(* Logix 5000 project; controller Motion_Axis_AOIs_AMCI_RSLogix_V31 vendor 1 type 14 code 108 rev 31.11; software revision 31.02; part 7 of 7 *)
(* tags used below, declared in another part *)
   AMCI_MA_Circular_Follower_SMD34E2 : AMCI_MA_SD_SMD_Circular_Follower;
   AMCI_MA_Linear_Follower_SMD34E2 : AMCI_MA_SD_SMD_Linear_Follower;
   AMCI_MA_Reset_Driver_Fault : AMCI_MA_Reset_Driver_Fault;
   AMCI_MA_Reset_Driver_Faults_SMD34E2 : AMCI_MA_Reset_Driver_Fault;
   AMCI_MAFR_SMD34E2 : AMCI_MAFR;
   AMCI_MAFR_SV160E2 : AMCI_MAFR;
   AMCI_MAFR_SV400E2 : AMCI_MAFR;
   AMCI_MAH_SMD34E2 : AMCI_MAH;
   AMCI_MAH_SV160E2 : AMCI_MAH;
   AMCI_MAH_SV400E2 : AMCI_MAH;
   AMCI_MAJ_SMD34E2 : AMCI_MAJ;
   AMCI_MAJ_SV160E2 : AMCI_MAJ;
   AMCI_MAJ_SV400E2 : AMCI_MAJ;
   AMCI_MAM_SMD34E2 : AMCI_MAM;
   AMCI_MAM_SV160E2 : AMCI_MAM;
   AMCI_MAM_SV400E2 : AMCI_MAM;
   AMCI_MAS_SMD34E2 : AMCI_MAS;
   AMCI_MAS_SV160E2 : AMCI_MAS;
   AMCI_MAS_SV400E2 : AMCI_MAS;
   AMCI_MRP_SMD34E2 : AMCI_MRP;
   AMCI_MRP_SV160E2 : AMCI_MRP;
   AMCI_MRP_SV400E2 : AMCI_MRP;
   AMCI_MSO_Preset_to_Absolute_Encoder : AMCI_MSO_and_Preset_to_Absolute_Encoder;
   AMCI_SV160E2_Circular_Follower : AMCI_MA_SV_Circular_Follower;
   AMCI_SV16E2_Linear_Follower : AMCI_MA_SV_Linear_Follower;
   AMCI_SV400E2_Circular_Follower : AMCI_MA_SV_Circular_Follower;
   AMCI_SV400E2_Linear_Follower : AMCI_MA_SV_Linear_Follower;
   AMCI_SMD34E2_input_data : AMCI_Motion_Axis_Input_Data;
   AMCI_SMD34E2_output_data : AMCI_Motion_Axis_Output_Data;
   AMCI_SV160E2_input_data : AMCI_Motion_Axis_Input_Data;
   AMCI_SV160E2_output_data : AMCI_Motion_Axis_Output_Data;
   AMCI_SV4000E2_input_data : AMCI_Motion_Axis_Input_Data;
   AMCI_SV400E2_output_data : AMCI_Motion_Axis_Output_Data;
   comment_coil : DINT;
   Main_Power : BOOL;   // 0=Remove Main Power 1=Apply Main Power
   Run_AMCI_SMD34E2 : DINT;
   Run_AMCI_SV160E2 : DINT;
   Run_AMCI_SV400E2 : DINT;
   Sample_Motion_Axis : AXIS_VIRTUAL;
(* MainProgram, continued *)

ROUTINE SMD34E2   (* ladder *)
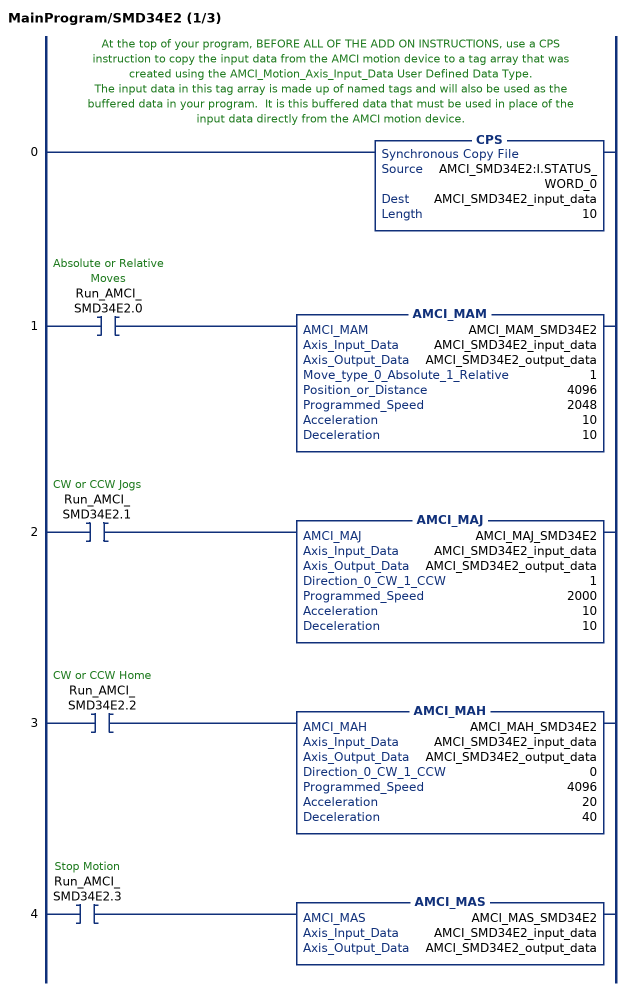
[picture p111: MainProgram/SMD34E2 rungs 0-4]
   // At the top of your program, BEFORE ALL OF THE ADD ON INSTRUCTIONS, use a CPS instruction to copy the input data from the AMCI motion device to a tag array that was created using the AMCI_Motion_Axis_Input_Data User Defined Data Type.
   // The input data in this tag array is made up of named tags and will also be used as the buffered data in your program.  It is this buffered data that must be used in place of the input data directly from the AMCI motion device.
   0: CPS(AMCI_SMD34E2:I.STATUS_WORD_0,AMCI_SMD34E2_input_data,10);
   1: XIC(Run_AMCI_SMD34E2.0)AMCI_MAM(AMCI_MAM_SMD34E2,AMCI_SMD34E2_input_data,AMCI_SMD34E2_output_data,1,4096,2048,10,10);
   2: XIC(Run_AMCI_SMD34E2.1)AMCI_MAJ(AMCI_MAJ_SMD34E2,AMCI_SMD34E2_input_data,AMCI_SMD34E2_output_data,1,2000,10,10);
   3: XIC(Run_AMCI_SMD34E2.2)AMCI_MAH(AMCI_MAH_SMD34E2,AMCI_SMD34E2_input_data,AMCI_SMD34E2_output_data,0,4096,20,40);
   4: XIC(Run_AMCI_SMD34E2.3)AMCI_MAS(AMCI_MAS_SMD34E2,AMCI_SMD34E2_input_data,AMCI_SMD34E2_output_data);
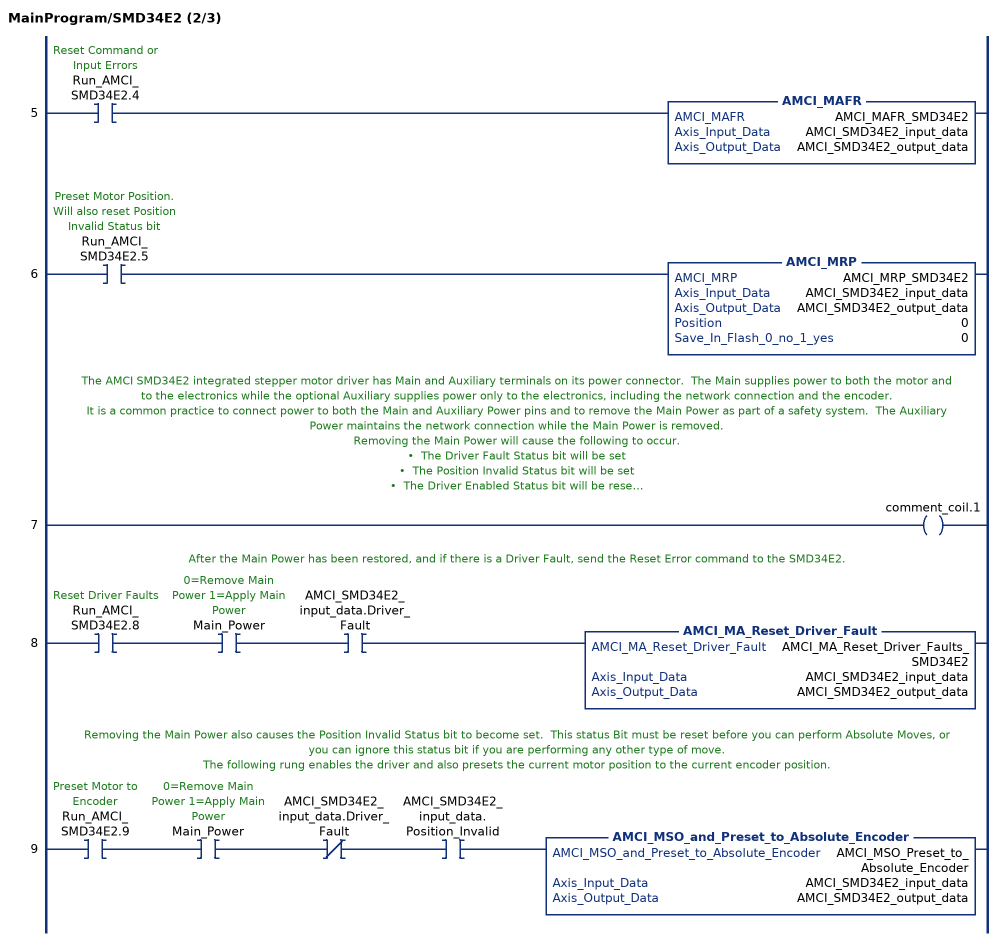
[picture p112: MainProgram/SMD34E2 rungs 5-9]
   5: XIC(Run_AMCI_SMD34E2.4)AMCI_MAFR(AMCI_MAFR_SMD34E2,AMCI_SMD34E2_input_data,AMCI_SMD34E2_output_data);
   6: XIC(Run_AMCI_SMD34E2.5)AMCI_MRP(AMCI_MRP_SMD34E2,AMCI_SMD34E2_input_data,AMCI_SMD34E2_output_data,0,0);
   // The AMCI SMD34E2 integrated stepper motor driver has Main and Auxiliary terminals on its power connector.  The Main supplies power to both the motor and to the electronics while the optional Auxiliary supplies power only to the electronics, including the network connection and the encoder.
   // It is a common practice to connect power to both the Main and Auxiliary Power pins and to remove the Main Power as part of a safety system.  The Auxiliary Power maintains the network connection while the Main Power is removed.
   // Removing the Main Power will cause the following to occur.
   // •	The Driver Fault Status bit will be set
   // •	The Position Invalid Status bit will be set
   // •	The Driver Enabled Status bit will be reset
   // The following two rungs show the action that you should take while the Main Power is removed and the steps needed to recover after the Main Power has been restored.
   7: OTE(comment_coil.1);
   // After the Main Power has been restored, and if there is a Driver Fault, send the Reset Error command to the SMD34E2.
   8: XIC(Run_AMCI_SMD34E2.8)XIC(Main_Power)XIC(AMCI_SMD34E2_input_data.Driver_Fault)AMCI_MA_Reset_Driver_Fault(AMCI_MA_Reset_Driver_Faults_SMD34E2,AMCI_SMD34E2_input_data,AMCI_SMD34E2_output_data);
   // Removing the Main Power also causes the Position Invalid Status bit to become set.  This status Bit must be reset before you can perform Absolute Moves, or you can ignore this status bit if you are performing any other type of move.
   // The following rung enables the driver and also presets the current motor position to the current encoder position.
   9: XIC(Run_AMCI_SMD34E2.9)XIC(Main_Power)XIO(AMCI_SMD34E2_input_data.Driver_Fault)XIC(AMCI_SMD34E2_input_data.Position_Invalid)AMCI_MSO_and_Preset_to_Absolute_Encoder(AMCI_MSO_Preset_to_Absolute_Encoder,AMCI_SMD34E2_input_data,AMCI_SMD34E2_output_data);
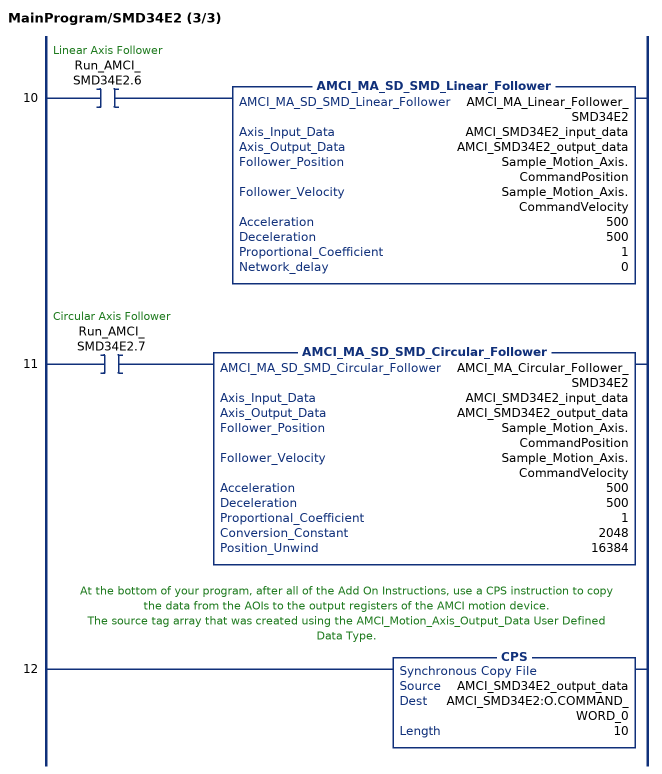
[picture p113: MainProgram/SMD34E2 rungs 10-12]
   10: XIC(Run_AMCI_SMD34E2.6)AMCI_MA_SD_SMD_Linear_Follower(AMCI_MA_Linear_Follower_SMD34E2,AMCI_SMD34E2_input_data,AMCI_SMD34E2_output_data,Sample_Motion_Axis.CommandPosition,Sample_Motion_Axis.CommandVelocity,500,500,1,0);
   11: XIC(Run_AMCI_SMD34E2.7)AMCI_MA_SD_SMD_Circular_Follower(AMCI_MA_Circular_Follower_SMD34E2,AMCI_SMD34E2_input_data,AMCI_SMD34E2_output_data,Sample_Motion_Axis.CommandPosition,Sample_Motion_Axis.CommandVelocity,500,500,1,2048,16384);
   // At the bottom of your program, after all of the Add On Instructions, use a CPS instruction to copy the data from the AOIs to the output registers of the AMCI motion device.
   // The source tag array that was created using the AMCI_Motion_Axis_Output_Data User Defined Data Type.
   12: CPS(AMCI_SMD34E2_output_data,AMCI_SMD34E2:O.COMMAND_WORD_0,10);
END_ROUTINE

ROUTINE SV160E2   (* ladder *)
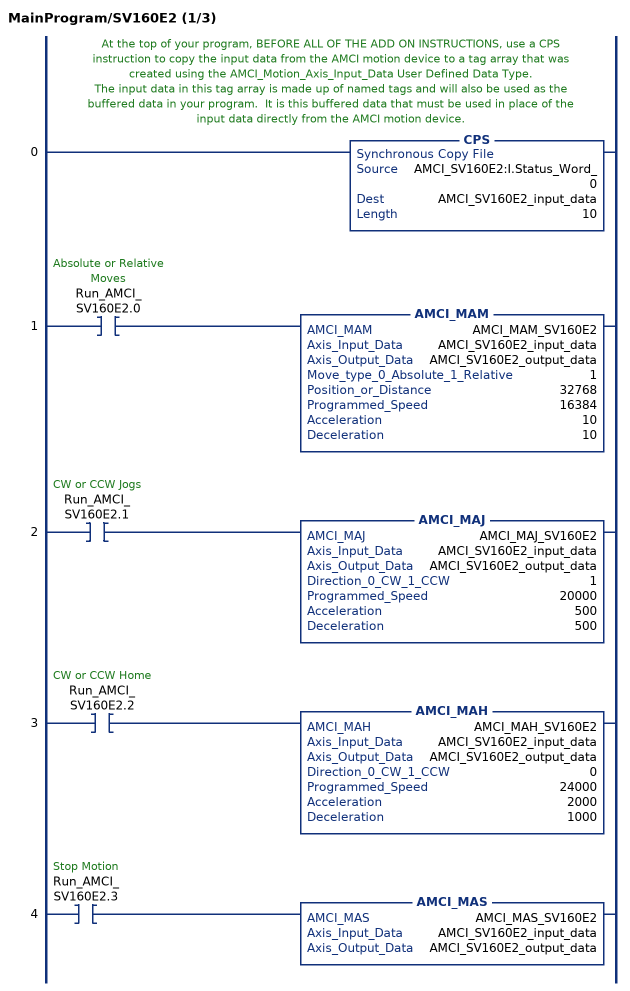
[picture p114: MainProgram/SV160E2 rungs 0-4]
   // At the top of your program, BEFORE ALL OF THE ADD ON INSTRUCTIONS, use a CPS instruction to copy the input data from the AMCI motion device to a tag array that was created using the AMCI_Motion_Axis_Input_Data User Defined Data Type.
   // The input data in this tag array is made up of named tags and will also be used as the buffered data in your program.  It is this buffered data that must be used in place of the input data directly from the AMCI motion device.
   0: CPS(AMCI_SV160E2:I.Status_Word_0,AMCI_SV160E2_input_data,10);
   1: XIC(Run_AMCI_SV160E2.0)AMCI_MAM(AMCI_MAM_SV160E2,AMCI_SV160E2_input_data,AMCI_SV160E2_output_data,1,32768,16384,10,10);
   2: XIC(Run_AMCI_SV160E2.1)AMCI_MAJ(AMCI_MAJ_SV160E2,AMCI_SV160E2_input_data,AMCI_SV160E2_output_data,1,20000,500,500);
   3: XIC(Run_AMCI_SV160E2.2)AMCI_MAH(AMCI_MAH_SV160E2,AMCI_SV160E2_input_data,AMCI_SV160E2_output_data,0,24000,2000,1000);
   4: XIC(Run_AMCI_SV160E2.3)AMCI_MAS(AMCI_MAS_SV160E2,AMCI_SV160E2_input_data,AMCI_SV160E2_output_data);
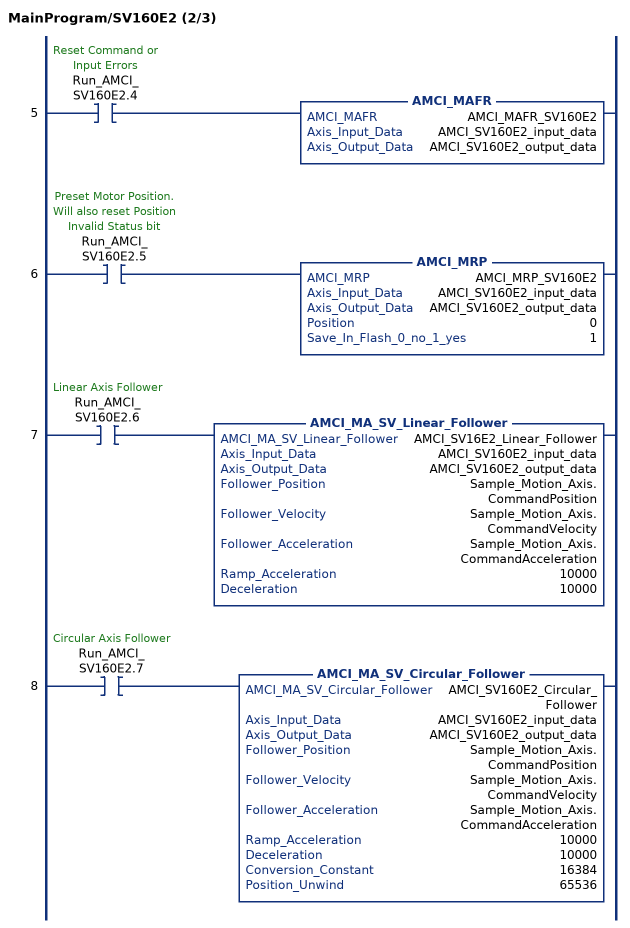
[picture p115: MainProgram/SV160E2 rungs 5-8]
   5: XIC(Run_AMCI_SV160E2.4)AMCI_MAFR(AMCI_MAFR_SV160E2,AMCI_SV160E2_input_data,AMCI_SV160E2_output_data);
   6: XIC(Run_AMCI_SV160E2.5)AMCI_MRP(AMCI_MRP_SV160E2,AMCI_SV160E2_input_data,AMCI_SV160E2_output_data,0,1);
   7: XIC(Run_AMCI_SV160E2.6)AMCI_MA_SV_Linear_Follower(AMCI_SV16E2_Linear_Follower,AMCI_SV160E2_input_data,AMCI_SV160E2_output_data,Sample_Motion_Axis.CommandPosition,Sample_Motion_Axis.CommandVelocity,Sample_Motion_Axis.CommandAcceleration,10000,10000);
   8: XIC(Run_AMCI_SV160E2.7)AMCI_MA_SV_Circular_Follower(AMCI_SV160E2_Circular_Follower,AMCI_SV160E2_input_data,AMCI_SV160E2_output_data,Sample_Motion_Axis.CommandPosition,Sample_Motion_Axis.CommandVelocity,Sample_Motion_Axis.CommandAcceleration,10000,10000,16384,65536);
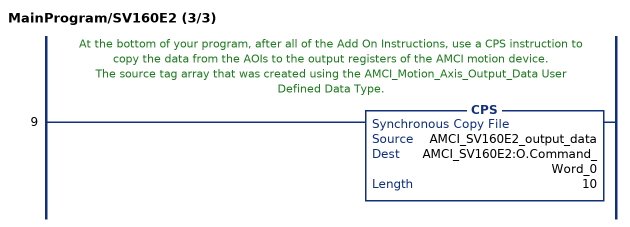
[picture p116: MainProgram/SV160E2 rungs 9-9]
   // At the bottom of your program, after all of the Add On Instructions, use a CPS instruction to copy the data from the AOIs to the output registers of the AMCI motion device.
   // The source tag array that was created using the AMCI_Motion_Axis_Output_Data User Defined Data Type.
   9: CPS(AMCI_SV160E2_output_data,AMCI_SV160E2:O.Command_Word_0,10);
END_ROUTINE

ROUTINE SV400E2   (* ladder *)
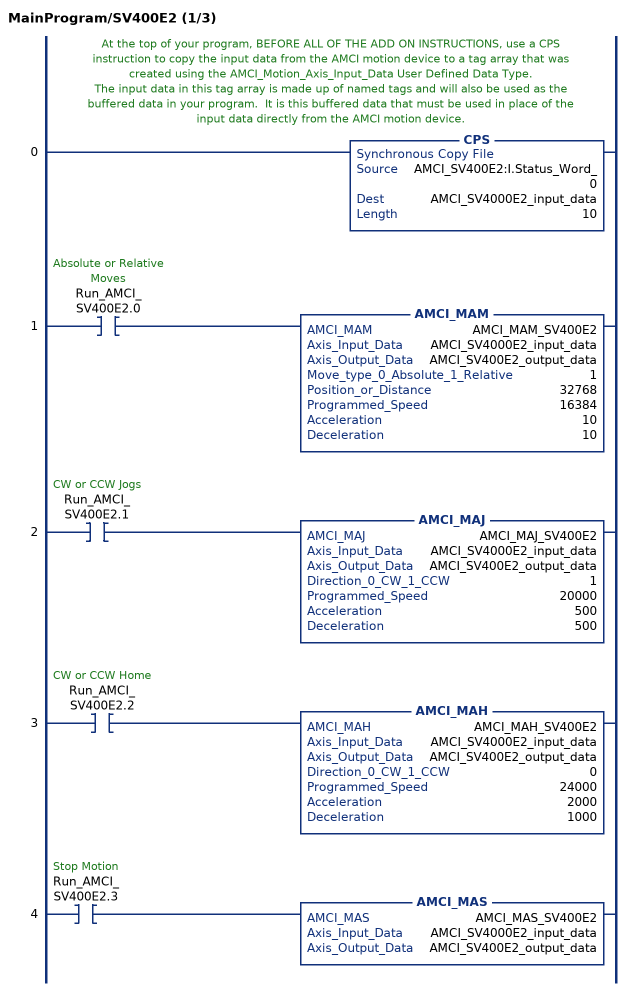
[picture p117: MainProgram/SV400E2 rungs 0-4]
   // At the top of your program, BEFORE ALL OF THE ADD ON INSTRUCTIONS, use a CPS instruction to copy the input data from the AMCI motion device to a tag array that was created using the AMCI_Motion_Axis_Input_Data User Defined Data Type.
   // The input data in this tag array is made up of named tags and will also be used as the buffered data in your program.  It is this buffered data that must be used in place of the input data directly from the AMCI motion device.
   0: CPS(AMCI_SV400E2:I.Status_Word_0,AMCI_SV4000E2_input_data,10);
   1: XIC(Run_AMCI_SV400E2.0)AMCI_MAM(AMCI_MAM_SV400E2,AMCI_SV4000E2_input_data,AMCI_SV400E2_output_data,1,32768,16384,10,10);
   2: XIC(Run_AMCI_SV400E2.1)AMCI_MAJ(AMCI_MAJ_SV400E2,AMCI_SV4000E2_input_data,AMCI_SV400E2_output_data,1,20000,500,500);
   3: XIC(Run_AMCI_SV400E2.2)AMCI_MAH(AMCI_MAH_SV400E2,AMCI_SV4000E2_input_data,AMCI_SV400E2_output_data,0,24000,2000,1000);
   4: XIC(Run_AMCI_SV400E2.3)AMCI_MAS(AMCI_MAS_SV400E2,AMCI_SV4000E2_input_data,AMCI_SV400E2_output_data);
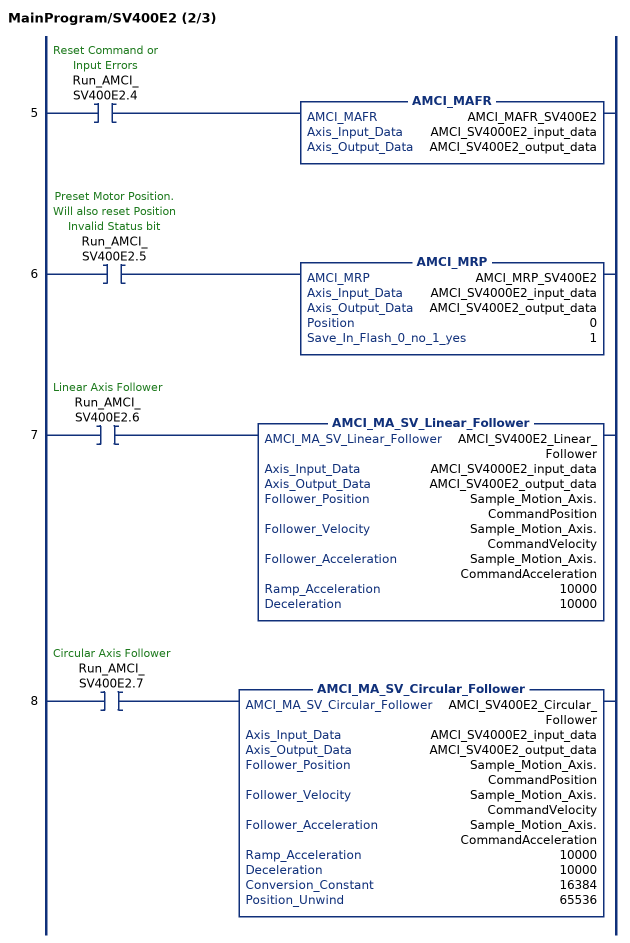
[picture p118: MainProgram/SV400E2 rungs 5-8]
   5: XIC(Run_AMCI_SV400E2.4)AMCI_MAFR(AMCI_MAFR_SV400E2,AMCI_SV4000E2_input_data,AMCI_SV400E2_output_data);
   6: XIC(Run_AMCI_SV400E2.5)AMCI_MRP(AMCI_MRP_SV400E2,AMCI_SV4000E2_input_data,AMCI_SV400E2_output_data,0,1);
   7: XIC(Run_AMCI_SV400E2.6)AMCI_MA_SV_Linear_Follower(AMCI_SV400E2_Linear_Follower,AMCI_SV4000E2_input_data,AMCI_SV400E2_output_data,Sample_Motion_Axis.CommandPosition,Sample_Motion_Axis.CommandVelocity,Sample_Motion_Axis.CommandAcceleration,10000,10000);
   8: XIC(Run_AMCI_SV400E2.7)AMCI_MA_SV_Circular_Follower(AMCI_SV400E2_Circular_Follower,AMCI_SV4000E2_input_data,AMCI_SV400E2_output_data,Sample_Motion_Axis.CommandPosition,Sample_Motion_Axis.CommandVelocity,Sample_Motion_Axis.CommandAcceleration,10000,10000,16384,65536);
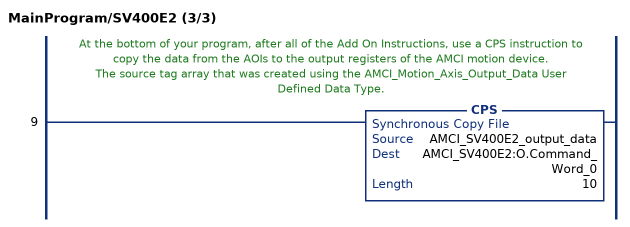
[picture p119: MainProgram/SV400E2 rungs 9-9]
   // At the bottom of your program, after all of the Add On Instructions, use a CPS instruction to copy the data from the AOIs to the output registers of the AMCI motion device.
   // The source tag array that was created using the AMCI_Motion_Axis_Output_Data User Defined Data Type.
   9: CPS(AMCI_SV400E2_output_data,AMCI_SV400E2:O.Command_Word_0,10);
END_ROUTINE
END_PROGRAM
